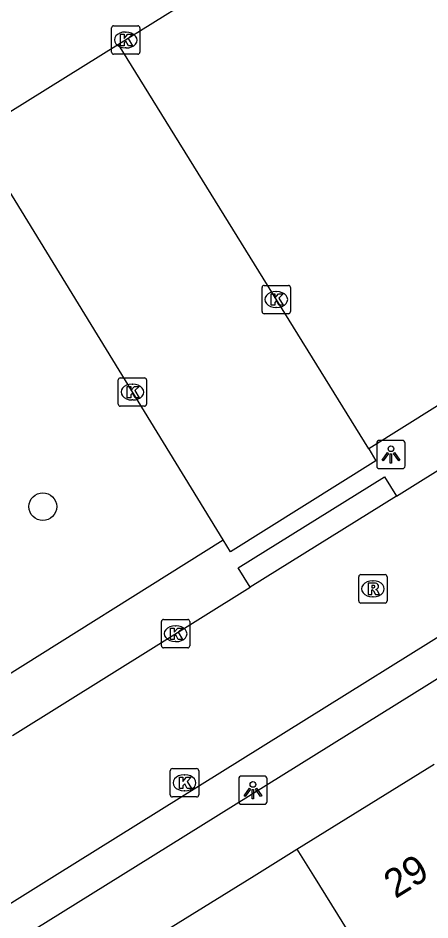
# Model space of a CAD drawing. Extents: x 160304 to 160954, y 383686 to 384161.
# Drawn here: x 160703.32 to 160717.85, y 383998.44 to 384030.21 of the extents above; entities that cross this region are included whole.
import ezdxf

# ---------------------------------------------------------------- set-up
doc = ezdxf.new("R2010")
doc.units = 0
for name, color, linetype in [('IMGEO_Boom', 7, 'Continuous'), ('IMGEO_Kolk', 7, 'Continuous'), ('IMGEO_Lichtpunt', 7, 'Continuous'), ('IMGEO_Pand', 7, 'Continuous'), ('IMGEO_Pand_nummerreeks', 7, 'Continuous'), ('IMGEO_Parkeervlak_open', 7, 'Continuous'), ('IMGEO_Rijbaan_lokaal_open', 7, 'Continuous'), ('IMGEO_Rioolput', 7, 'Continuous'), ('IMGEO_Voetpad_open', 7, 'Continuous')]:
    doc.layers.add(name, color=color, linetype=linetype)

msp = doc.modelspace()

# ---------------------------------------------------------------- linework, layer by layer
at = {"layer": 'IMGEO_Boom'}
msp.add_circle((160704.196, 384013.001), 0.489, dxfattribs=at)
at = {"layer": 'IMGEO_Kolk'}
for p, q in [((160706.619, 384029.013), (160706.619, 384029.865)), ((160706.694, 384029.939), (160707.546, 384029.939)), ((160707.107, 384029.719), (160707.132, 384029.719)), ((160707.62, 384029.865), (160707.62, 384029.013)), ((160707.13, 384029.159), (160707.105, 384029.159)), ((160707.546, 384028.939), (160706.694, 384028.939)), ((160711.928, 384019.87), (160711.928, 384020.722)), ((160712.003, 384020.796), (160712.855, 384020.796)), ((160712.416, 384020.576), (160712.441, 384020.576)), ((160712.929, 384020.722), (160712.929, 384019.87)), ((160712.439, 384020.016), (160712.414, 384020.016)), ((160712.855, 384019.796), (160712.003, 384019.796)), ((160706.854, 384016.612), (160706.854, 384017.464)), ((160706.929, 384017.538), (160707.781, 384017.538)), ((160707.855, 384017.464), (160707.855, 384016.612)), ((160707.342, 384017.318), (160707.367, 384017.318)), ((160707.365, 384016.758), (160707.34, 384016.758)), ((160707.781, 384016.538), (160706.929, 384016.538)), ((160708.379, 384008.099), (160708.379, 384008.951)), ((160708.454, 384009.025), (160709.306, 384009.025)), ((160708.867, 384008.805), (160708.892, 384008.805)), ((160709.38, 384008.951), (160709.38, 384008.099)), ((160708.89, 384008.245), (160708.865, 384008.245)), ((160709.306, 384008.025), (160708.454, 384008.025)), ((160708.691, 384002.847), (160708.691, 384003.699)), ((160708.766, 384003.773), (160709.618, 384003.773)), ((160709.692, 384003.699), (160709.692, 384002.847)), ((160709.179, 384003.553), (160709.204, 384003.553)), ((160709.618, 384002.773), (160708.766, 384002.773)), ((160709.202, 384002.993), (160709.177, 384002.993))]:
    msp.add_line(p, q, dxfattribs=at)
for points in [[(160706.619, 384029.013), (160706.619, 384029.865)], [(160706.694, 384029.939), (160707.546, 384029.939)], [(160707.62, 384029.865), (160707.62, 384029.013)], [(160706.94, 384029.639), (160707.063, 384029.639), (160707.063, 384029.488), (160707.193, 384029.639), (160707.357, 384029.639), (160707.211, 384029.488), (160707.364, 384029.239), (160707.212, 384029.239), (160707.127, 384029.403), (160707.063, 384029.336), (160707.063, 384029.239), (160706.94, 384029.239), (160706.94, 384029.639)], [(160707.546, 384028.939), (160706.694, 384028.939)], [(160711.928, 384019.87), (160711.928, 384020.722)], [(160712.003, 384020.796), (160712.855, 384020.796)], [(160712.929, 384020.722), (160712.929, 384019.87)], [(160712.249, 384020.496), (160712.372, 384020.496), (160712.372, 384020.345), (160712.502, 384020.496), (160712.666, 384020.496), (160712.52, 384020.345), (160712.673, 384020.096), (160712.521, 384020.096), (160712.436, 384020.26), (160712.372, 384020.193), (160712.372, 384020.096), (160712.249, 384020.096), (160712.249, 384020.496)], [(160712.855, 384019.796), (160712.003, 384019.796)], [(160706.854, 384016.612), (160706.854, 384017.464)], [(160706.929, 384017.538), (160707.781, 384017.538)], [(160707.855, 384017.464), (160707.855, 384016.612)], [(160707.175, 384017.238), (160707.298, 384017.238), (160707.298, 384017.087), (160707.428, 384017.238), (160707.592, 384017.238), (160707.446, 384017.087), (160707.599, 384016.838), (160707.447, 384016.838), (160707.362, 384017.002), (160707.298, 384016.935), (160707.298, 384016.838), (160707.175, 384016.838), (160707.175, 384017.238)], [(160707.781, 384016.538), (160706.929, 384016.538)], [(160708.379, 384008.099), (160708.379, 384008.951)], [(160708.454, 384009.025), (160709.306, 384009.025)], [(160709.38, 384008.951), (160709.38, 384008.099)], [(160708.7, 384008.725), (160708.823, 384008.725), (160708.823, 384008.574), (160708.953, 384008.725), (160709.117, 384008.725), (160708.971, 384008.574), (160709.124, 384008.325), (160708.972, 384008.325), (160708.887, 384008.489), (160708.823, 384008.422), (160708.823, 384008.325), (160708.7, 384008.325), (160708.7, 384008.725)], [(160709.306, 384008.025), (160708.454, 384008.025)], [(160708.691, 384002.847), (160708.691, 384003.699)], [(160708.766, 384003.773), (160709.618, 384003.773)], [(160709.692, 384003.699), (160709.692, 384002.847)], [(160709.012, 384003.473), (160709.135, 384003.473), (160709.135, 384003.322), (160709.265, 384003.473), (160709.429, 384003.473), (160709.283, 384003.322), (160709.436, 384003.073), (160709.284, 384003.073), (160709.199, 384003.237), (160709.135, 384003.17), (160709.135, 384003.073), (160709.012, 384003.073), (160709.012, 384003.473)], [(160709.618, 384002.773), (160708.766, 384002.773)]]:
    msp.add_lwpolyline(points, dxfattribs=at)
for centre, start, end in [((160706.696, 384029.863), 91.552, 178.448), ((160706.696, 384029.863), 91.552, 178.448), ((160707.544, 384029.863), 1.552, 88.448), ((160707.544, 384029.863), 1.552, 88.448), ((160706.696, 384029.015), 181.552, 268.448), ((160706.696, 384029.015), 181.552, 268.448), ((160707.544, 384029.015), 271.552, 358.448), ((160707.544, 384029.015), 271.552, 358.448), ((160712.005, 384020.72), 91.552, 178.448), ((160712.005, 384020.72), 91.552, 178.448), ((160712.853, 384020.72), 1.552, 88.448), ((160712.853, 384020.72), 1.552, 88.448), ((160712.005, 384019.872), 181.552, 268.448), ((160712.005, 384019.872), 181.552, 268.448), ((160712.853, 384019.872), 271.552, 358.448), ((160712.853, 384019.872), 271.552, 358.448), ((160706.931, 384017.462), 91.552, 178.448), ((160706.931, 384017.462), 91.552, 178.448), ((160707.779, 384017.462), 1.552, 88.448), ((160707.779, 384017.462), 1.552, 88.448), ((160706.931, 384016.614), 181.552, 268.448), ((160706.931, 384016.614), 181.552, 268.448), ((160707.779, 384016.614), 271.552, 358.448), ((160707.779, 384016.614), 271.552, 358.448), ((160708.456, 384008.949), 91.552, 178.448), ((160708.456, 384008.949), 91.552, 178.448), ((160709.304, 384008.949), 1.552, 88.448), ((160709.304, 384008.949), 1.552, 88.448), ((160708.456, 384008.101), 181.552, 268.448), ((160708.456, 384008.101), 181.552, 268.448), ((160709.304, 384008.101), 271.552, 358.448), ((160709.304, 384008.101), 271.552, 358.448), ((160708.768, 384003.697), 91.552, 178.448), ((160708.768, 384003.697), 91.552, 178.448), ((160709.616, 384003.697), 1.552, 88.448), ((160709.616, 384003.697), 1.552, 88.448), ((160708.768, 384002.849), 181.552, 268.448), ((160708.768, 384002.849), 181.552, 268.448), ((160709.616, 384002.849), 271.552, 358.448), ((160709.616, 384002.849), 271.552, 358.448)]:
    msp.add_arc(centre, 0.0765, start, end, dxfattribs=at)
for centre, major_axis, ratio, start_param, end_param in [((160707.106, 384029.439), (-0.387, 0.002), 0.722429, 4.712389, 7.853982), ((160707.131, 384029.439), (-0.39, 0.002), 0.717154, 1.570796, 4.712389), ((160712.415, 384020.296), (-0.387, 0.002), 0.722429, 4.712389, 7.853982), ((160712.44, 384020.296), (-0.39, 0.002), 0.717154, 1.570796, 4.712389), ((160707.341, 384017.038), (-0.387, 0.002), 0.722429, 4.712389, 7.853982), ((160707.366, 384017.038), (-0.39, 0.002), 0.717154, 1.570796, 4.712389), ((160708.866, 384008.525), (-0.387, 0.002), 0.722429, 4.712389, 7.853982), ((160708.891, 384008.525), (-0.39, 0.002), 0.717154, 1.570796, 4.712389), ((160709.178, 384003.273), (-0.387, 0.002), 0.722429, 4.712389, 7.853982), ((160709.203, 384003.273), (-0.39, 0.002), 0.717154, 1.570796, 4.712389)]:
    msp.add_ellipse(centre, major_axis=major_axis, ratio=ratio, start_param=start_param, end_param=end_param, dxfattribs=at)
at = {"layer": 'IMGEO_Lichtpunt'}
for p, q in [((160715.972, 384015.24), (160715.972, 384014.433)), ((160715.972, 384015.24), (160715.972, 384014.433)), ((160716.874, 384015.335), (160716.066, 384015.335)), ((160716.874, 384015.335), (160716.066, 384015.335)), ((160716.968, 384014.433), (160716.968, 384015.24)), ((160716.968, 384014.433), (160716.968, 384015.24)), ((160716.066, 384014.339), (160716.874, 384014.339)), ((160716.066, 384014.339), (160716.874, 384014.339)), ((160711.105, 384003.416), (160711.105, 384002.609)), ((160711.105, 384003.416), (160711.105, 384002.609)), ((160712.007, 384003.511), (160711.199, 384003.511)), ((160712.007, 384003.511), (160711.199, 384003.511)), ((160712.101, 384002.609), (160712.101, 384003.416)), ((160712.101, 384002.609), (160712.101, 384003.416)), ((160711.199, 384002.515), (160712.007, 384002.515)), ((160711.199, 384002.515), (160712.007, 384002.515))]:
    msp.add_line(p, q, dxfattribs=at)
for points in [[(160716.346, 384014.904), (160716.385, 384014.876), (160716.197, 384014.614), (160716.159, 384014.641), (160716.346, 384014.904)], [(160716.448, 384014.856), (160716.495, 384014.856), (160716.495, 384014.534), (160716.448, 384014.534), (160716.448, 384014.856)], [(160716.558, 384014.876), (160716.596, 384014.903), (160716.783, 384014.641), (160716.744, 384014.613), (160716.558, 384014.876)], [(160711.479, 384003.08), (160711.518, 384003.052), (160711.33, 384002.79), (160711.292, 384002.817), (160711.479, 384003.08)], [(160711.581, 384003.032), (160711.628, 384003.032), (160711.628, 384002.71), (160711.581, 384002.71), (160711.581, 384003.032)], [(160711.691, 384003.052), (160711.729, 384003.079), (160711.916, 384002.817), (160711.877, 384002.789), (160711.691, 384003.052)]]:
    msp.add_lwpolyline(points, dxfattribs=at)
for centre in [(160716.471, 384015.038), (160711.604, 384003.214)]:
    msp.add_circle(centre, 0.0994, dxfattribs=at)
for centre, start, end in [((160716.066, 384015.24), 90, 180), ((160716.066, 384015.24), 90, 180), ((160716.874, 384015.24), 0, 90), ((160716.874, 384015.24), 0, 90), ((160716.066, 384014.433), 180, 270), ((160716.066, 384014.433), 180, 270), ((160716.874, 384014.433), 270, 0), ((160716.874, 384014.433), 270, 360), ((160711.199, 384003.416), 90, 180), ((160711.199, 384003.416), 90, 180), ((160712.007, 384003.416), 0, 90), ((160712.007, 384003.416), 0, 90), ((160711.199, 384002.609), 180, 270), ((160711.199, 384002.609), 180, 270), ((160712.007, 384002.609), 270, 0), ((160712.007, 384002.609), 270, 360)]:
    msp.add_arc(centre, 0.0946, start, end, dxfattribs=at)
at = {"layer": 'IMGEO_Pand'}
for points in [[(160713.157, 384000.931), (160717.995, 384003.923)], [(160708.32, 383997.939), (160711.652, 384000), (160713.157, 384000.931)], [(160713.157, 384000.931), (160713.735, 384000), (160717.217, 383994.395)]]:
    msp.add_lwpolyline(points, dxfattribs=at)
at = {"layer": 'IMGEO_Parkeervlak_open'}
msp.add_lwpolyline([(160715.343, 384034.554), (160706.863, 384029.281)], dxfattribs=at)
at = {"layer": 'IMGEO_Rijbaan_lokaal_open'}
for points in [[(160706.863, 384029.281), (160701.775, 384026.118)], [(160715.687, 384015.035), (160706.863, 384029.281)], [(160710.558, 384011.827), (160701.775, 384026.118)], [(160716.664, 384013.373), (160725.171, 384018.672)], [(160698.671, 383996.302), (160698.705, 383996.323), (160704.611, 384000), (160727.392, 384014.184), (160727.407, 384014.193), (160727.891, 384014.455), (160728.396, 384014.672), (160728.919, 384014.843), (160729.454, 384014.967), (160729.999, 384015.042), (160730.548, 384015.069), (160731.098, 384015.046), (160731.643, 384014.974), (160732.179, 384014.854), (160732.703, 384014.686), (160733.21, 384014.473), (160733.695, 384014.215), (160734.156, 384013.914), (160734.588, 384013.574), (160734.987, 384013.196), (160735.352, 384012.785), (160735.678, 384012.342)], [(160715.687, 384015.035), (160715.944, 384014.62), (160710.817, 384011.406), (160710.558, 384011.827)], [(160716.664, 384013.373), (160711.511, 384010.162)], [(160703.128, 384004.94), (160711.511, 384010.162)]]:
    msp.add_lwpolyline(points, dxfattribs=at)
at = {"layer": 'IMGEO_Rioolput'}
for p, q in [((160715.335, 384009.679), (160715.335, 384010.531)), ((160715.41, 384010.605), (160716.262, 384010.605)), ((160715.823, 384010.385), (160715.848, 384010.385)), ((160716.336, 384010.531), (160716.336, 384009.679)), ((160715.846, 384009.825), (160715.821, 384009.825)), ((160716.262, 384009.605), (160715.41, 384009.605))]:
    msp.add_line(p, q, dxfattribs=at)
for points in [[(160715.335, 384009.679), (160715.335, 384010.531)], [(160715.41, 384010.605), (160716.262, 384010.605)], [(160716.336, 384010.531), (160716.336, 384009.679)], [(160715.924, 384010.303), (160715.672, 384010.305), (160715.672, 384009.905)], [(160715.672, 384009.905), (160715.796, 384009.905), (160715.796, 384010.067), (160715.807, 384010.067)], [(160715.85, 384010.224), (160715.796, 384010.224), (160715.796, 384010.143)], [(160715.796, 384010.143), (160715.848, 384010.143)], [(160715.854, 384010.038), (160715.925, 384009.905), (160716.065, 384009.905), (160716, 384010.031)], [(160716.262, 384009.605), (160715.41, 384009.605)]]:
    msp.add_lwpolyline(points, dxfattribs=at)
for centre, radius, start, end in [((160715.412, 384010.529), 0.0765, 91.552, 178.448), ((160715.412, 384010.529), 0.0765, 91.552, 178.448), ((160716.26, 384010.529), 0.0765, 1.552, 88.448), ((160716.26, 384010.529), 0.0765, 1.552, 88.448), ((160715.806, 384010.014), 0.0533, 26.0293, 88.6989), ((160715.832, 384010.332), 0.19, 274.7715, 282.9687), ((160715.856, 384010.128), 0.0964, 77.0061, 93.1865), ((160715.87, 384010.185), 0.0378, 276.6634, 79.6772), ((160715.923, 384010.193), 0.109, 350.3612, 89.416), ((160715.921, 384010.193), 0.112, 277.5842, 350.9817), ((160715.905, 384009.978), 0.108, 29.5134, 73.7905), ((160715.412, 384009.681), 0.0765, 181.552, 268.448), ((160715.412, 384009.681), 0.0765, 181.552, 268.448), ((160716.26, 384009.681), 0.0765, 271.552, 358.448), ((160716.26, 384009.681), 0.0765, 271.552, 358.448)]:
    msp.add_arc(centre, radius, start, end, dxfattribs=at)
for centre, major_axis, ratio, start_param, end_param in [((160715.822, 384010.105), (-0.387, 0.002), 0.722429, 4.712389, 7.853982), ((160715.847, 384010.105), (-0.39, 0.002), 0.717154, 1.570796, 4.712389)]:
    msp.add_ellipse(centre, major_axis=major_axis, ratio=ratio, start_param=start_param, end_param=end_param, dxfattribs=at)
at = {"layer": 'IMGEO_Voetpad_open'}
for points in [[(160724.118, 384020.31), (160715.687, 384015.035)], [(160711.511, 384010.162), (160711.088, 384010.841), (160716.24, 384014.052), (160716.664, 384013.373)], [(160687.05, 383987.636), (160706.936, 384000), (160726.422, 384012.115), (160727.787, 384009.979)], [(160702.191, 384006.592), (160710.558, 384011.827)]]:
    msp.add_lwpolyline(points, dxfattribs=at)

# ---------------------------------------------------------------- texts
at = {"layer": 'IMGEO_Pand_nummerreeks'}
msp.add_text('29', height=1, rotation=31.9018, dxfattribs=at).set_placement((160716.629, 383999.173))

doc.saveas('drawing.dxf')
